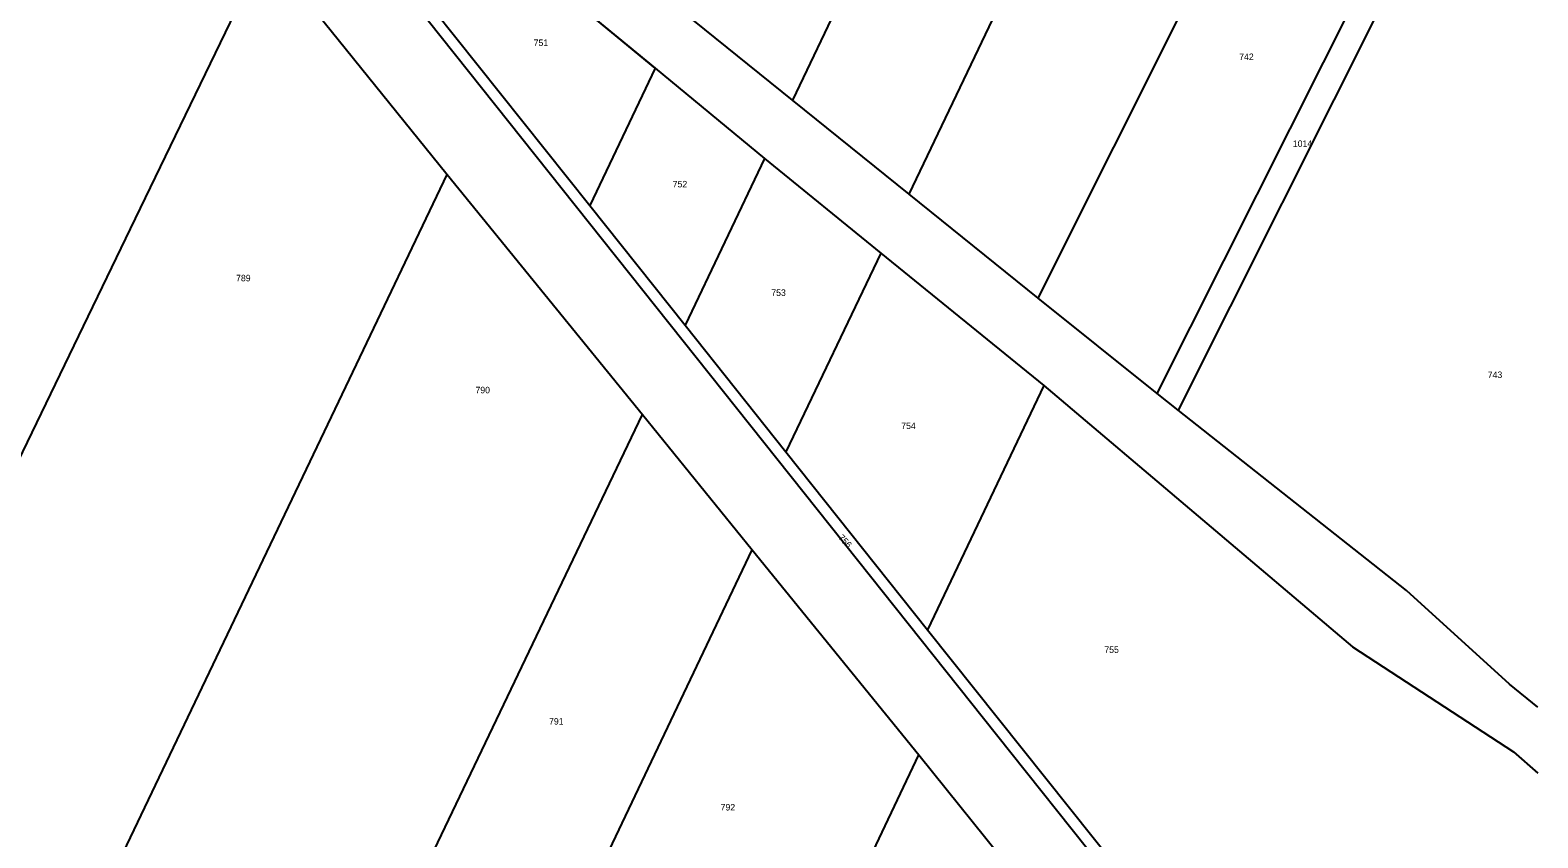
# Model space of a CAD drawing. Extents: x -504601 to -503665, y -1079870 to -1078626.
# Drawn here: x -504059.2 to -503665.3, y -1079659 to -1079448.1 of the extents above; entities that cross this region are included whole.
import ezdxf

# ---------------------------------------------------------------- set-up
doc = ezdxf.new("R2010")
doc.units = 0
for name, color, linetype in [('Hranice parcel', 7, 'Continuous'), ('Parcelní čísla', 7, 'Continuous'), ('Vrstva 54', 7, 'Continuous')]:
    doc.layers.add(name, color=color, linetype=linetype)

msp = doc.modelspace()

# ---------------------------------------------------------------- linework, layer by layer
at = {"layer": 'Hranice parcel'}
for p, q in [((-503775.28, -1079288.96), (-503860.04, -1079466.37)), ((-503829.57, -1079490.93), (-503746.84, -1079317.77)), ((-503795.86, -1079518.12), (-503713.84, -1079354.4)), ((-503764.74, -1079543.01), (-503689.81, -1079393.87)), ((-503686.06, -1079401.52), (-503759.31, -1079547.3)), ((-503942.64, -1079419.51), (-503895.86, -1079458.07)), ((-503997.67, -1079427.08), (-503950.22, -1079485.75)), ((-503953.77, -1079442.68), (-503912.97, -1079493.9)), ((-503860.04, -1079466.37), (-503888.76, -1079443.21)), ((-503895.86, -1079458.07), (-503912.97, -1079493.9)), ((-503895.86, -1079458.07), (-503867.31, -1079481.6)), ((-503829.57, -1079490.93), (-503860.04, -1079466.37)), ((-503867.31, -1079481.6), (-503888.1, -1079525.12)), ((-503867.31, -1079481.6), (-503836.94, -1079506.3)), ((-503950.22, -1079485.75), (-503899.25, -1079548.46)), ((-503795.86, -1079518.12), (-503829.57, -1079490.93)), ((-503912.97, -1079493.9), (-503888.1, -1079525.12)), ((-503836.94, -1079506.3), (-503861.75, -1079558.21)), ((-503836.94, -1079506.3), (-503794.37, -1079540.85)), ((-503764.74, -1079543.01), (-503795.86, -1079518.12)), ((-503888.1, -1079525.12), (-503861.75, -1079558.21)), ((-503794.37, -1079540.85), (-503824.73, -1079604.69)), ((-503759.31, -1079547.3), (-503764.74, -1079543.01)), ((-503899.25, -1079548.46), (-503870.57, -1079583.75)), ((-503861.75, -1079558.21), (-503824.73, -1079604.69)), ((-503870.57, -1079583.75), (-503827.05, -1079637.31)), ((-503827.05, -1079637.31), (-503785.46, -1079688.81))]:
    msp.add_line(p, q, dxfattribs=at)
for points in [[(-504131.58, -1079709.87), (-504110.18, -1079659.69), (-504032.95, -1079500.02), (-503997.67, -1079427.08)], [(-503697.84, -1079765.64), (-503779.17, -1079666.7), (-503806.76, -1079632.06), (-503843.08, -1079586.46), (-503955.21, -1079445.68)], [(-504133.72, -1079869.85), (-504130.18, -1079862.44), (-504053.56, -1079702.06), (-503975.76, -1079539.21), (-503950.22, -1079485.75)], [(-503794.37, -1079540.85), (-503713.69, -1079609.09), (-503671.67, -1079636.49), (-503665.31, -1079642.13)], [(-503665.31, -1079624.83), (-503672.75, -1079618.9), (-503699.64, -1079594.38), (-503759.31, -1079547.3)], [(-504052.8, -1079869.85), (-504043.32, -1079850.01), (-503965, -1079686.08), (-503899.25, -1079548.46)], [(-504006.66, -1079869.85), (-503993.46, -1079842.09), (-503916.36, -1079680.01), (-503870.57, -1079583.75)], [(-503824.73, -1079604.69), (-503775.32, -1079666.65), (-503696.41, -1079762.65)], [(-503937.05, -1079869.85), (-503919.87, -1079833.53), (-503842.14, -1079669.21), (-503827.05, -1079637.31)]]:
    msp.add_lwpolyline(points, dxfattribs=at)
at = {"layer": 'Vrstva 54'}
msp.add_lwpolyline([(-503895.86, -1079458.07), (-503942.64, -1079419.51), (-503946.4, -1079416.88), (-503945.84, -1079414.89), (-503977.25, -1079388.9), (-504014.44, -1079358.14), (-504038.99, -1079330.47), (-504044.97, -1079331.7), (-504048.32, -1079336.41), (-504164.13, -1079193.65), (-504189.98, -1079161.66), (-504303.4, -1079021.3)], dxfattribs=at)

# ---------------------------------------------------------------- texts
at = {"layer": 'Parcelní čísla'}
for s, p in [('751', (-503927.65, -1079452.24)), ('742', (-503743.33, -1079455.91)), ('1014', (-503729.32, -1079478.59)), ('752', (-503891.32, -1079489.16)), ('789', (-504005.38, -1079513.68)), ('753', (-503865.56, -1079517.49)), ('743', (-503678.4, -1079538.93)), ('790', (-503942.85, -1079542.92)), ('754', (-503831.62, -1079552.25)), ('755', (-503778.56, -1079610.7)), ('791', (-503923.62, -1079629.42)), ('792', (-503878.8, -1079651.84))]:
    msp.add_text(s, height=1.7, dxfattribs=at).set_placement(p)
msp.add_text('756', height=1.7, rotation=314, dxfattribs=at).set_placement((-503848.21, -1079580.74))

doc.saveas('drawing.dxf')
